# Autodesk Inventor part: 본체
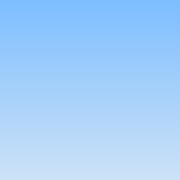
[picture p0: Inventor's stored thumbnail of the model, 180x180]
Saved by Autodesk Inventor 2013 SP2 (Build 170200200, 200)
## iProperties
Created: 2026-07
Part Number: 본체
Material: Generic
Document SubType Name: Modeling
Designer: a
Density: 1 g/cm^3
Author: a
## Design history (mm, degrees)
